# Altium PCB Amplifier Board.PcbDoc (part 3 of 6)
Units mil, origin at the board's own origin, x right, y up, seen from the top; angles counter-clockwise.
Board outline 6000 x 2640 mil, 6 copper layers (Top Layer, GND, VCC, BASES, GND (Plane3), Bottom Layer), stack 63.9 mil thick; 884 components, 484 nets, 2029 pads, 464 vias.
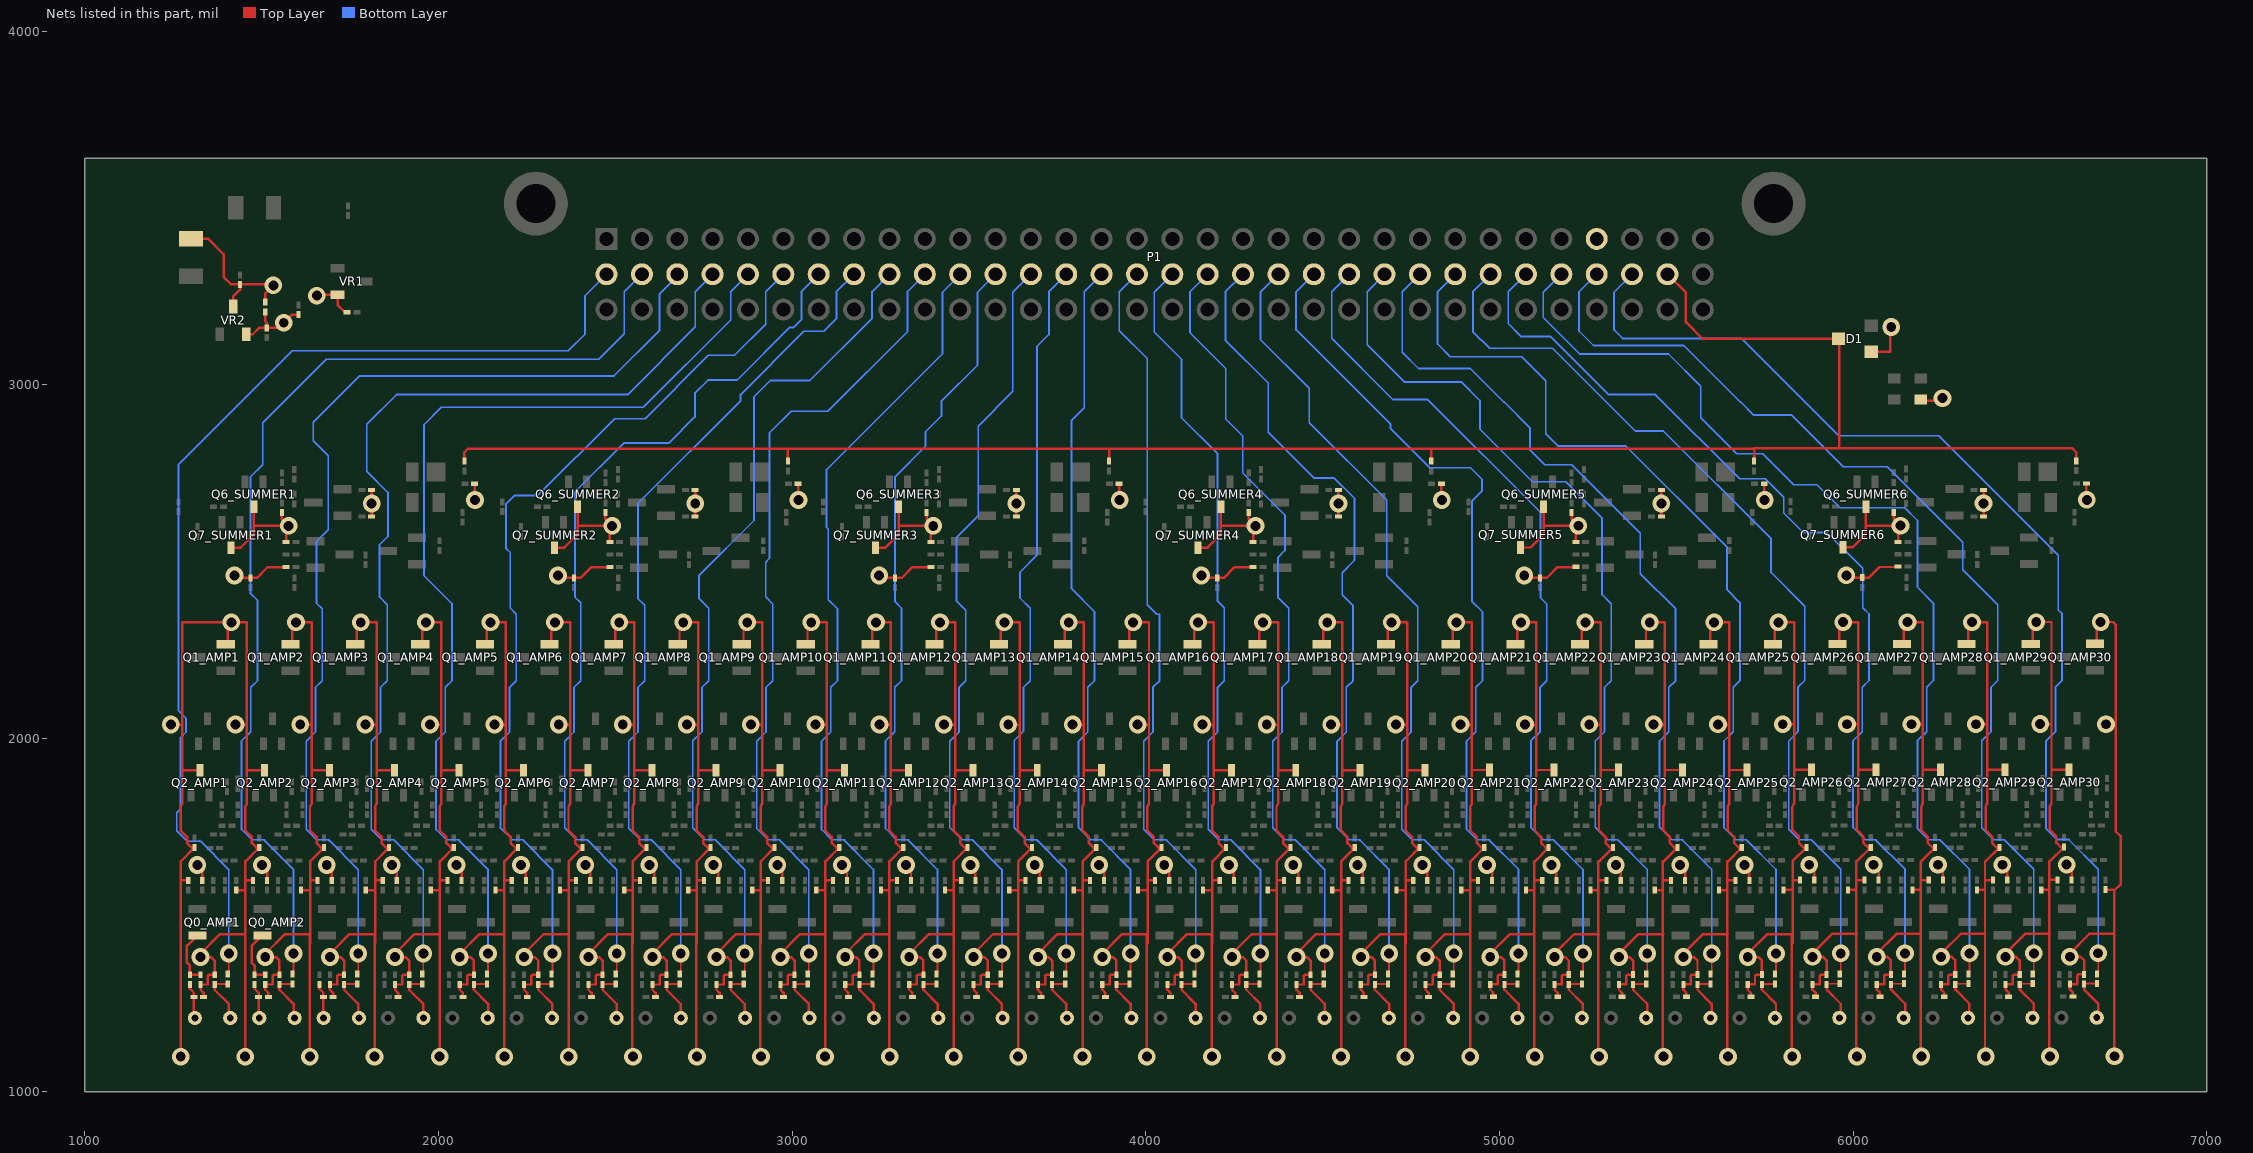
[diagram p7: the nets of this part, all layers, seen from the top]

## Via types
v1: diameter 50, hole 28, Top Layer to Bottom Layer, 433 vias
v2: diameter 50, hole 28, Top Layer to Bottom Layer, tented top, 31 vias

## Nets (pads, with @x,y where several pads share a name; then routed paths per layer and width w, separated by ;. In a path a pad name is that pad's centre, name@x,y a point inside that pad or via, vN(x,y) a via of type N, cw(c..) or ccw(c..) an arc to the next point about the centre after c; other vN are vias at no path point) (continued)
BASE2: C11.2 R23.1 R26.2 RBi_AMP1.1 RBi_AMP2.1 RBi_AMP3.1 RBi_AMP4.1 RBi_AMP5.1 RBi_AMP6.1 RBi_AMP7.1 RBi_AMP8.1 RBi_AMP9.1 RBi_AMP10.1 RBi_AMP11.1 RBi_AMP12.1 RBi_AMP13.1 RBi_AMP14.1 RBi_AMP15.1 RBi_AMP16.1 RBi_AMP17.1 RBi_AMP18.1 RBi_AMP19.1 RBi_AMP20.1 RBi_AMP21.1 RBi_AMP22.1 RBi_AMP23.1 RBi_AMP24.1 RBi_AMP25.1 RBi_AMP26.1 RBi_AMP27.1 RBi_AMP28.1 RBi_AMP29.1 RBi_AMP30.1 VR2.3 | length 1924.2
  Top Layer w7: R23.1@1300,3413.15 1347.85,3413.15 1392,3369 1392,3305 1412.4,3284.6 v1@1529.4,3284.6 ; v1(1318,1642) 1332,1628 RBi_AMP1.1@1332,1598.56 ; VR2.3@1419,3221.37 1419,3249 1439,3269 R26.2@1439,3283.22 ; v1(1501,1642) 1515,1628 RBi_AMP2.1@1515,1598.56 ; C11.2@1510,3233.78 1510,3258 v1(1533,3281) ; v1(1684,1642) 1698,1628 RBi_AMP3.1@1698,1598.56 ; v1(1868,1642) 1882,1628 RBi_AMP4.1@1882,1598.56 ; v1(2051,1642) 2065,1628 RBi_AMP5.1@2065,1598.56 ; v1(2233,1642) 2247,1628 RBi_AMP6.1@2247,1598.56 ; v1(2415,1642) 2429,1628 RBi_AMP7.1@2429,1598.56 ; v1(2596,1642) 2610,1628 RBi_AMP8.1@2610,1598.56 ; v1(2777,1642) 2791,1628 RBi_AMP9.1@2791,1598.56 ; v1(2958,1642) 2972,1628 RBi_AMP10.1@2972,1598.56 ; v1(3141,1642) 3155,1628 RBi_AMP11.1@3155,1598.56 ; v1(3322,1642) 3336,1628 RBi_AMP12.1@3336,1598.56 ; v1(3504,1642) 3518,1628 RBi_AMP13.1@3518,1598.56 ; v1(3686,1642) 3700,1628 RBi_AMP14.1@3700,1598.56 ; v1(3868,1642) 3882,1628 RBi_AMP15.1@3882,1598.56 ; v1(4052,1642) 4066,1628 RBi_AMP16.1@4066,1598.56 ; v1(4235,1642) 4249,1628 RBi_AMP17.1@4249,1598.56 ; v1(4417,1642) 4431,1628 RBi_AMP18.1@4431,1598.56 ; v1(4599,1642) 4613,1628 RBi_AMP19.1@4613,1598.56 ; v1(4782,1642) 4796,1628 RBi_AMP20.1@4796,1598.56 ; v1(4965,1642.1) 4979,1628.1 RBi_AMP21.1@4979,1598.66 ; v1(5147,1642.1) 5161,1628.1 RBi_AMP22.1@5161,1598.66 ; v1(5329,1642.1) 5343,1628.1 RBi_AMP23.1@5343,1598.66 ; v1(5511,1642.1) 5525,1628.1 RBi_AMP24.1@5525,1598.66 ; v1(5693,1642.1) 5707,1628.1 RBi_AMP25.1@5707,1598.66 ; v1(5876,1642.57) 5890,1628.57 RBi_AMP26.1@5890,1599.13 ; v1(6058,1642.57) 6072,1628.57 RBi_AMP27.1@6072,1599.13 ; v1(6240,1642.57) 6254,1628.57 RBi_AMP28.1@6254,1599.13 ; v1(6422,1642.57) 6436,1628.57 RBi_AMP29.1@6436,1599.13 ; v1(6604,1643) 6618,1629 RBi_AMP30.1@6618,1599.56
BIAS1_SUMMER1: P1.B1 R18_AMP1.1 | length 3053.7
  Top Layer w5: R18_AMP1.1@1407,1334.83 v1(1407,1391.43) v1@1407,1392.43
  Bottom Layer w5: 1324.56,1711.44 1326.71,1709.29 ; 1328.27,1709.29 1326.71,1709.29 ; v1@1407,1381.56 v1(1407,1391.43) 1407,1629 1327.49,1708.51 1326.71,1709.29 ; P1.B1@2475,3312.36 2414,3251.36 2414,3143 2367,3096 1586,3096 1265,2775 1265,2078 1286,2057 1286,2017.99 1270.5,2002.49 1270.5,1800.5 1260,1790 1260,1739 1289.71,1709.29 1326.71,1709.29
BIAS1_SUMMER2: P1.B6 R18_AMP6.1 | length 2554
  Top Layer w5: R18_AMP6.1@2322,1334.83 v1(2322,1391.43) v1@2322,1392.43
  Bottom Layer w5: 2239.56,1711.44 2322,1629 v1(2322,1391.43) v1@2322,1381.56 ; 2239.56,1713 2209,1713 2174.84,1747.16 2174.84,1991.84 2201,2018 2201,2144 2220,2163 2220,2351 2202.5,2368.5 2202.5,2525.5 2190.5,2537.5 2190.5,2662.5 2215,2687 2281,2687 2498,2904 2584,2904 2763,3083 2837,3083 2925,3171 2925,3262.36 P1.B6@2975,3312.36
BIAS1_SUMMER3: P1.B11 R18_AMP11.1 | length 2265
  Top Layer w5: R18_AMP11.1@3230,1334.83 v1(3230,1391.43) v1@3230,1392.43
  Bottom Layer w5: 3147.56,1711.44 3230,1629 v1(3230,1391.43) v1@3230,1381.56 ; 3147.56,1713 3112.43,1713 3082.84,1742.59 3082.84,1991.84 3109,2018 3109,2144 3128,2163 3128,2366 3102,2392 3102,2592 3097,2597 3097,2760 3425,3088 3425,3261 3475.68,3311.68 P1.B11@3482,3318
BIAS1_SUMMER4: P1.B16 R18_AMP16.1 | length 2159.7
  Top Layer w5: R18_AMP16.1@4141,1334.83 v1(4141,1391.43) v1@4141,1392.43
  Bottom Layer w5: P1.B16@3975,3312.36 3925,3262.36 3925,3153 4004,3074 4004,2378 4031,2351 4039,2351 4039,2163 4020,2144 4020,2018 3993.84,1991.84 3993.84,1742.59 4023.43,1713 4058.56,1713 ; 4058.56,1711.44 4141,1629 v1(4141,1391.43) v1@4141,1381.56
BIAS1_SUMMER5: P1.B21 R18_AMP21.1 | length 2417.4
  Top Layer w5: R18_AMP21.1@5054,1334.93 v1(5054,1391.53) v1@5054,1392.53
  Bottom Layer w5: P1.B21@4475,3312.36 4425,3262.36 4425,3155 4692.2,2887.8 4692.2,2875.8 4803,2765 4918,2765 4951,2732 4951,2700 4922,2671 4922,2388 4952,2358 4952,2163.1 4933,2144.1 4933,2018.38 4906.84,1992.22 4906.84,1742.69 4936.43,1713.1 4971.56,1713.1 ; 4971.56,1711.54 5054,1629.1 v1(5054,1391.53) v1@5054,1381.66
BIAS1_SUMMER6: P1.B26 R18_AMP26.1 | length 2646.3
  Top Layer w5: R18_AMP26.1@5965,1335.4 v1(5965,1392) v1@5965,1393
  Bottom Layer w5: P1.B26@4975,3312.36 4925,3262.36 4925,3150 4972,3103 5150,3103 5384,2869 5463,2869 5768,2564 5768,2469 5863,2374 5863,2163.57 5844,2144.57 5844,2018.62 5817.84,1992.47 5817.84,1743.16 5847.43,1713.57 5882.56,1713.57 ; 5882.56,1712.01 5965,1629.57 v1(5965,1392) v1@5965,1382.13
BIAS2_SUMMER1: P1.B2 R18_AMP2.1 | length 3005
  Top Layer w5: R18_AMP2.1@1590,1334.83 v1(1590,1391.43) v1@1590,1392.43
  Bottom Layer w5: 1507.56,1711.44 1590,1629 v1(1590,1391.43) v1@1590,1381.56 ; 1507.56,1713 1472.43,1713 1442.84,1742.59 1442.84,1992.84 1469,2019 1469,2144 1488,2163 1488,2390.44 1468,2410.44 1468,2739 1503,2774 1503,2892 1683,3072 2453,3072 2525,3144 2525,3262.36 P1.B2@2575,3312.36
BIAS2_SUMMER2: P1.B7 R18_AMP7.1 | length 2505.3
  Top Layer w5: R18_AMP7.1@2504,1334.83 v1(2504,1391.43) v1@2504,1392.43
  Bottom Layer w5: 2421.56,1711.44 2504,1629 v1(2504,1391.43) v1@2504,1381.56 ; 2421.56,1713 2391,1713 2356.84,1747.16 2356.84,1991.84 2383,2018 2383,2144 2402,2163 2402,2383 2386,2399 2386,2697 2524,2835 2651,2835 2725,2909 2725,2976 2762,3013 2844,3013 2993,3162 3004,3162 3026,3184 3026,3263.36 P1.B7@3075,3312.36
BIAS2_SUMMER3: P1.B12 R18_AMP12.1 | length 2210.7
  Top Layer w5: R18_AMP12.1@3411,1334.83 v1(3411,1391.43) v1@3411,1392.43
  Bottom Layer w5: 3328.56,1711.44 3411,1629 v1(3411,1391.43) v1@3411,1381.56 ; 3328.56,1713 3296,1713 3263.84,1745.16 3263.84,1992.84 3290,2019 3290,2144 3309,2163 3309,2368 3291,2386 3291,2740 3377,2826 3377,2866.5 3422,2911.5 3422,2953 3524,3055 3524,3261.36 P1.B12@3575,3312.36
BIAS2_SUMMER4: P1.B17 R18_AMP17.1 | length 2190.2
  Top Layer w5: R18_AMP17.1@4324,1334.83 v1(4324,1391.43) v1@4324,1392.43
  Bottom Layer w5: P1.B17@4075,3312.36 4024,3261.36 4024,3149 4101,3072 4101,2907 4203,2805 4203,2388 4222,2369 4222,2163 4203,2144 4203,2018 4176.84,1991.84 4176.84,1742.59 4206.43,1713 4241.56,1713 ; 4241.56,1711.44 4324,1629 v1(4324,1391.43) v1@4324,1381.56
BIAS2_SUMMER5: P1.B22 R18_AMP22.1 | length 2413.3
  Top Layer w5: R18_AMP22.1@5236,1334.93 v1(5236,1391.53) v1@5236,1392.53
  Bottom Layer w5: P1.B22@4575,3312.36 4526,3263.36 4526,3131 4699,2958 4797,2958 5116,2639 5116,2398 5134,2380 5134,2163.1 5115,2144.1 5115,2018.96 5088.84,1992.8 5088.84,1748.16 5123.9,1713.1 5153.56,1713.1 ; 5153.56,1711.54 5236,1629.1 v1(5236,1391.53) v1@5236,1381.66
BIAS2_SUMMER6: P1.B27 R18_AMP27.1 | length 2734.6
  Top Layer w5: R18_AMP27.1@6147,1335.4 v1(6147,1392) v1@6147,1393
  Bottom Layer w5: P1.B27@5075,3312.36 5025,3262.36 5025,3173 5062,3136 5145.28,3136 5309.28,2972 5441,2972 5679,2734 5752,2734 5804,2682 5804,2637.17 5859.17,2582 5926,2582 6027,2481 6027,2369.57 6045,2351.57 6045,2163.57 6026,2144.57 6026,2019 5999.84,1992.84 5999.84,1748.16 6034.43,1713.57 6064.56,1713.57 ; 6064.56,1712.01 6147,1629.57 v1(6147,1392) v1@6147,1382.13
BIAS3_SUMMER1: P1.B3 R18_AMP3.1 | length 2979.5
  Top Layer w5: R18_AMP3.1@1773,1334.83 v1(1773,1391.43) v1@1773,1392.43
  Bottom Layer w5: 1690.56,1711.44 1773,1629 v1(1773,1391.43) v1@1773,1381.56 ; 1690.56,1713 1655.43,1713 1625.84,1742.59 1625.84,1992.2 1652,2018.36 1652,2144 1671,2163 1671,2366 1655,2382 1655,2556.9 1688,2589.9 1688,2799 1646,2841 1646,2894 1777,3025 2496,3025 2625,3154 2625,3257 2677.68,3309.68 P1.B3@2684,3316
BIAS3_SUMMER2: P1.B8 R18_AMP8.1 | length 2378.7
  Top Layer w5: R18_AMP8.1@2685,1334.83 v1(2685,1391.43) v1@2685,1392.43
  Bottom Layer w5: 2602.56,1711.44 2685,1629 v1(2685,1391.43) v1@2685,1381.56 ; 2602.56,1713 2571,1713 2537.84,1746.16 2537.84,1991.84 2564,2018 2564,2144 2583,2163 2583,2376 2564,2395 2564,2665 2854,2955 2854,2972 3033,3151 3089,3151 3125,3187 3125,3262.36 P1.B8@3175,3312.36
BIAS3_SUMMER3: P1.B13 R18_AMP13.1 | length 2181.7
  Top Layer w5: R18_AMP13.1@3593,1334.83 v1(3593,1391.43) v1@3593,1392.43
  Bottom Layer w5: 3510.56,1711.44 3593,1629 v1(3593,1391.43) v1@3593,1381.56 ; 3510.56,1713 3480.79,1713 3445.84,1747.94 3445.84,1991.84 3472,2018 3472,2144 3491,2163 3491,2362 3465,2388 3465,2568.95 3526,2629.95 3526,2883 3624,2981 3624,3261.36 P1.B13@3675,3312.36
BIAS3_SUMMER4: P1.B18 R18_AMP18.1 | length 2236.8
  Top Layer w5: R18_AMP18.1@4506,1334.83 v1(4506,1391.43) v1@4506,1392.43
  Bottom Layer w5: P1.B18@4175,3312.36 4125,3262.36 4125,3147 4226,3046 4226,2903 4274,2855 4274,2750.5 4393.44,2631.06 4393.44,2531.44 4374,2512 4374,2398 4404,2368 4404,2163 4385,2144 4385,2018 4358.84,1991.84 4358.84,1747.16 4393,1713 4423.56,1713 ; 4423.56,1711.44 4506,1629 v1(4506,1391.43) v1@4506,1381.56
BIAS3_SUMMER5: P1.B23 R18_AMP23.1 | length 2539.1
  Top Layer w5: R18_AMP23.1@5418,1334.93 v1(5418,1391.53) v1@5418,1392.53
  Bottom Layer w5: P1.B23@4675,3312.36 4626,3263.36 4626,3113 4731,3008 4892,3008 4945,2955 4945,2874 5093.46,2725.54 5187.12,2725.54 5290.26,2622.4 5290.26,2406.74 5316,2381 5316,2163.1 5297,2144.1 5297,2018.77 5270.84,1992.61 5270.84,1748.16 5305.9,1713.1 5335.56,1713.1 ; 5335.56,1711.54 5418,1629.1 v1(5418,1391.53) v1@5418,1381.66
BIAS3_SUMMER6: P1.B28 R18_AMP28.1 | length 2898.7
  Top Layer w5: R18_AMP28.1@6329,1335.4 v1(6329,1392) v1@6329,1393
  Bottom Layer w5: P1.B28@5175,3312.36 5124,3261.36 5124,3190 5227,3087 5478,3087 5569,2996 5569,2906.7 5670.7,2805 5744.7,2805 5832.7,2717 5898,2717 5963,2652 6146.16,2652 6182,2616.16 6182,2427 6227,2382 6227,2163.57 6208,2144.57 6208,2019 6181.84,1992.84 6181.84,1746.16 6214.43,1713.57 6246.56,1713.57 ; 6246.56,1712.01 6329,1629.57 v1(6329,1392) v1@6329,1382.13
BIAS4_SUMMER1: P1.B4 R18_AMP4.1 | length 2919
  Top Layer w5: R18_AMP4.1@1957,1334.83 v1(1957,1391.43) v1@1957,1392.43
  Bottom Layer w5: 1874.56,1711.44 1957,1629 v1(1957,1391.43) v1@1957,1381.56 ; 1874.56,1713 1839.43,1713 1809.84,1742.59 1809.84,1991.84 1836,2018 1836,2144 1855,2163 1855,2378 1833,2400 1833,2547.09 1857,2571.09 1857,2695 1797,2755 1797,2888 1881,2972 2534.64,2972 2726,3163.36 2726,3263.36 P1.B4@2775,3312.36
BIAS4_SUMMER2: P1.B9 R18_AMP9.1 | length 2384.7
  Top Layer w5: R18_AMP9.1@2866,1334.83 v1(2866,1391.43) v1@2866,1392.43
  Bottom Layer w5: 2783.56,1711.44 2866,1629 v1(2866,1391.43) v1@2866,1381.56 ; 2783.56,1713 2753,1713 2718.84,1747.16 2718.84,1992.84 2745,2019 2745,2144 2764,2163 2764,2368 2736.23,2395.77 2736.23,2460.13 2892,2615.9 2892,2966 2938,3012 3050,3012 3226,3188 3226,3263.36 P1.B9@3275,3312.36
BIAS4_SUMMER3: P1.B14 R18_AMP14.1 | length 2150.5
  Top Layer w5: R18_AMP14.1@3775,1334.83 v1(3775,1391.43) v1@3775,1392.43
  Bottom Layer w5: 3692.56,1711.44 3775,1629 v1(3775,1391.43) v1@3775,1381.56 ; 3692.56,1713 3662,1713 3627.84,1747.16 3627.84,1993.84 3654,2020 3654,2144 3673,2163 3673,2368 3644.23,2396.77 3644.23,2469.79 3692,2517.56 3692,3108 3726,3142 3726,3263.36 P1.B14@3775,3312.36
BIAS4_SUMMER4: P1.B19 R18_AMP19.1 | length 2316.6
  Top Layer w5: R18_AMP19.1@4688,1334.83 v1(4688,1391.43) v1@4688,1392.43
  Bottom Layer w5: P1.B19@4275,3312.36 4225,3262.36 4225,3126 4346,3005 4346,2866 4476.1,2735.9 4533.1,2735.9 4590,2679 4590,2503.56 4555.23,2468.79 4555.23,2405.77 4586,2375 4586,2163 4567,2144 4567,2018 4540.84,1991.84 4540.84,1747.52 4575.36,1713 4605.56,1713 ; 4605.56,1711.44 4688,1629 v1(4688,1391.43) v1@4688,1381.56
BIAS4_SUMMER5: P1.B24 R18_AMP24.1 | length 2555.6
  Top Layer w5: R18_AMP24.1@5600,1334.93 v1(5600,1391.53) v1@5600,1392.53
  Bottom Layer w5: P1.B24@4775,3312.36 4725,3262.36 4725,3092 4771,3046 4917,3046 5012,2951 5013,2951 5086,2878 5086,2816 5128,2774 5204.5,2774 5398,2580.5 5398,2466 5498,2366 5498,2163.1 5479,2144.1 5479,2018.58 5452.84,1992.42 5452.84,1748.16 5487.9,1713.1 5517.56,1713.1 ; 5517.56,1711.54 5600,1629.1 v1(5600,1391.53) v1@5600,1381.66
BIAS4_SUMMER6: P1.B29 R18_AMP29.1 | length 2881.2
  Top Layer w5: R18_AMP29.1@6511,1335.4 v1(6511,1392) v1@6511,1393
  Bottom Layer w5: P1.B29@5275,3312.36 5225,3262.36 5225,3152 5266,3111 5521,3111 5681,2951 5682,2951 5719,2914 5826,2914 5972,2768 6097,2768 6310,2555 6310,2476.79 6409,2377.79 6409,2163.57 6390,2144.57 6390,2019 6363.84,1992.84 6363.84,1747.16 6397.43,1713.57 6428.56,1713.57 ; 6428.56,1712.01 6511,1629.57 v1(6511,1392) v1@6511,1382.13
BIAS5_SUMMER1: P1.B5 R18_AMP5.1 | length 2833.7
  Top Layer w5: R18_AMP5.1@2140,1334.83 v1(2140,1391.43) v1@2140,1392.43
  Bottom Layer w5: 2057.56,1711.44 2140,1629 v1(2140,1391.43) v1@2140,1381.56 ; 2057.56,1713 2022.43,1713 1992.84,1742.59 1992.84,1991.84 2019,2018 2019,2144 2038,2163 2038,2381 1959,2460 1959,2887 2008,2936 2579,2936 2826,3183 2826,3263.36 P1.B5@2875,3312.36
BIAS5_SUMMER2: P1.B10 R18_AMP10.1 | length 2341.2
  Top Layer w5: R18_AMP10.1@3047,1334.83 v1(3047,1391.43) v1@3047,1392.43
  Bottom Layer w5: 2964.56,1711.44 3047,1629 v1(3047,1391.43) v1@3047,1381.56 ; 2964.56,1713 2932,1713 2899.84,1745.16 2899.84,1991.84 2926,2018 2926,2144 2945,2163 2945,2380 2925,2400 2925,2498 2936,2509 2936,2864 2997,2925 3101,2925 3326,3150 3326,3263.36 P1.B10@3375,3312.36
BIAS5_SUMMER3: P1.B15 R18_AMP15.1 | length 2146.5
  Top Layer w5: R18_AMP15.1@3957,1334.83 v1(3957,1391.43) v1@3957,1392.43
  Bottom Layer w5: 3874.56,1711.44 3957,1629 v1(3957,1391.43) v1@3957,1381.56 ; 3874.56,1713 3844,1713 3809.84,1747.16 3809.84,1991.84 3836,2018 3836,2144 3855,2163 3855,2358 3790,2423 3790,2899 3826,2935 3826,3263.36 P1.B15@3875,3312.36
BIAS5_SUMMER4: P1.B20 R18_AMP20.1 | length 2292.5
  Top Layer w5: R18_AMP20.1@4871,1334.83 v1(4871,1391.43) v1@4871,1392.43
  Bottom Layer w5: P1.B20@4375,3312.36 4324,3261.36 4324,3128 4462,2990 4462,2893 4681,2674 4681,2460 4769,2372 4769,2163 4750,2144 4750,2018 4723.84,1991.84 4723.84,1742.59 4753.43,1713 4788.56,1713 ; 4788.56,1711.44 4871,1629 v1(4871,1391.43) v1@4871,1381.56
BIAS5_SUMMER5: P1.B25 R18_AMP25.1 | length 2689.7
  Top Layer w5: R18_AMP25.1@5782,1334.93 v1(5782,1391.53) v1@5782,1392.53
  Bottom Layer w5: P1.B25@4875,3312.36 4825,3262.36 4825,3115 4861,3079 5063,3079 5131,3011 5131,2861 5165,2827 5356.5,2827 5643.6,2539.91 5643.6,2420.4 5680,2384 5680,2163.1 5661,2144.1 5661,2018.77 5634.84,1992.61 5634.84,1747.16 5668.9,1713.1 5699.56,1713.1 ; 5699.56,1711.54 5782,1629.1 v1(5782,1391.53) v1@5782,1381.66
BIAS5_SUMMER6: P1.B30 R18_AMP30.1 | length 2994.7
  Top Layer w5: R18_AMP30.1@6693,1335.83 v1(6693,1392.43) v1@6693,1393.43
  Bottom Layer w5: P1.B30@5375,3312.36 5324,3261.36 5324,3155 5348,3131 5684,3131 5959,2856 6242,2856 6580,2518 6580,2363 ; 6580,2362.57 6580,2363 ; 6610.56,1712.44 6693,1630 v1(6693,1392.43) v1@6693,1382.56 ; 6610.56,1714 6576,1714 6545.84,1744.16 6545.84,1992.84 6572,2019 6572,2145 6591,2164 6591,2352 6580,2363
GAINMODE: D1.2 P1.B31 RG_SUMMER1.2 RG_SUMMER2.2 RG_SUMMER3.2 RG_SUMMER4.2 RG_SUMMER5.2 RG_SUMMER6.2 | length 5671.5
  Top Layer w7: RG_SUMMER1.2@2073,2783.78 2073,2809 2083,2819 3896,2819 ; RG_SUMMER2.2@2988,2783.78 2988,2817 ; RG_SUMMER3.2@3896,2783.78 3896,2819 ; RG_SUMMER4.2@4807,2783.78 4807,2817 ; P1.B31@5475,3312.36 5527,3260.36 5527,3177 5574,3130 D1.2@5958.74,3130 ; RG_SUMMER5.2@5720,2783.88 5720,2819 ; 5961,2821 D1.2@5961,3130 ; RG_SUMMER6.2@6631,2784.35 6631,2809 6620,2820 5720,2820 5720,2819 ; 3896,2819 5720,2819
GND: C1_AMP1.2 C1_AMP2.2 C1_AMP3.2 C1_AMP4.2 C1_AMP5.2 C1_AMP6.2 C1_AMP7.2 C1_AMP8.2 C1_AMP9.2 C1_AMP10.2 C1_AMP11.2 C1_AMP12.2 C1_AMP13.2 C1_AMP14.2 C1_AMP15.2 C1_AMP16.2 C1_AMP17.2 C1_AMP18.2 C1_AMP19.2 C1_AMP20.2 C1_AMP21.2 C1_AMP22.2 C1_AMP23.2 C1_AMP24.2 C1_AMP25.2 C1_AMP26.2 C1_AMP27.2 C1_AMP28.2 C1_AMP29.2 C1_AMP30.2 C3_AMP1.1 C3_AMP2.1 C3_AMP3.1 C3_AMP4.1 C3_AMP5.1 C3_AMP6.1 C3_AMP7.1 C3_AMP8.1 C3_AMP9.1 C3_AMP10.1 C3_AMP11.1 C3_AMP12.1 C3_AMP13.1 C3_AMP14.1 C3_AMP15.1 C3_AMP16.1 C3_AMP17.1 C3_AMP18.1 C3_AMP19.1 C3_AMP20.1 C3_AMP21.1 C3_AMP22.1 C3_AMP23.1 C3_AMP24.1 C3_AMP25.1 C3_AMP26.1 C3_AMP27.1 C3_AMP28.1 C3_AMP29.1 C3_AMP30.1 C10.1 C11.1 CBi_AMP1.2 CBi_AMP2.2 CBi_AMP3.2 CBi_AMP4.2 CBi_AMP5.2 CBi_AMP6.2 CBi_AMP7.2 CBi_AMP8.2 CBi_AMP9.2 CBi_AMP10.2 CBi_AMP11.2 CBi_AMP12.2 CBi_AMP13.2 CBi_AMP14.2 CBi_AMP15.2 CBi_AMP16.2 CBi_AMP17.2 CBi_AMP18.2 CBi_AMP19.2 CBi_AMP20.2 CBi_AMP21.2 CBi_AMP22.2 CBi_AMP23.2 CBi_AMP24.2 CBi_AMP25.2 CBi_AMP26.2 CBi_AMP27.2 CBi_AMP28.2 CBi_AMP29.2 CBi_AMP30.2 CBi_SUMMER1.2 CBi_SUMMER2.2 CBi_SUMMER3.2 CBi_SUMMER4.2 CBi_SUMMER5.2 CBi_SUMMER6.2 CG_SUMMER1.2 CG_SUMMER2.2 CG_SUMMER3.2 CG_SUMMER4.2 CG_SUMMER5.2 CG_SUMMER6.2 D1.1 P1.A29 Q1_AMP1.2 Q1_AMP2.2 Q1_AMP3.2 Q1_AMP4.2 Q1_AMP5.2 Q1_AMP6.2 Q1_AMP7.2 Q1_AMP8.2 Q1_AMP9.2 Q1_AMP10.2 Q1_AMP11.2 Q1_AMP12.2 Q1_AMP13.2 Q1_AMP14.2 Q1_AMP15.2 Q1_AMP16.2 Q1_AMP17.2 Q1_AMP18.2 Q1_AMP19.2 Q1_AMP20.2 Q1_AMP21.2 Q1_AMP22.2 Q1_AMP23.2 Q1_AMP24.2 Q1_AMP25.2 Q1_AMP26.2 Q1_AMP27.2 Q1_AMP28.2 Q1_AMP29.2 Q1_AMP30.2 Q2_AMP1.3 Q2_AMP2.3 Q2_AMP3.3 Q2_AMP4.3 Q2_AMP5.3 Q2_AMP6.3 Q2_AMP7.3 Q2_AMP8.3 Q2_AMP9.3 Q2_AMP10.3 Q2_AMP11.3 Q2_AMP12.3 Q2_AMP13.3 Q2_AMP14.3 Q2_AMP15.3 Q2_AMP16.3 Q2_AMP17.3 Q2_AMP18.3 Q2_AMP19.3 Q2_AMP20.3 Q2_AMP21.3 Q2_AMP22.3 Q2_AMP23.3 Q2_AMP24.3 Q2_AMP25.3 Q2_AMP26.3 Q2_AMP27.3 Q2_AMP28.3 Q2_AMP29.3 Q2_AMP30.3 Q6_SUMMER1.3 Q6_SUMMER2.3 Q6_SUMMER3.3 Q6_SUMMER4.3 Q6_SUMMER5.3 Q6_SUMMER6.3 Q7_SUMMER1.3 Q7_SUMMER2.3 Q7_SUMMER3.3 Q7_SUMMER4.3 Q7_SUMMER5.3 Q7_SUMMER6.3 R1_AMP1.1 R1_AMP2.1 R1_AMP3.1 R1_AMP4.1 R1_AMP5.1 R1_AMP6.1 R1_AMP7.1 R1_AMP8.1 R1_AMP9.1 R1_AMP10.1 R1_AMP11.1 R1_AMP12.1 R1_AMP13.1 R1_AMP14.1 R1_AMP15.1 R1_AMP16.1 R1_AMP17.1 R1_AMP18.1 R1_AMP19.1 R1_AMP20.1 R1_AMP21.1 R1_AMP22.1 R1_AMP23.1 R1_AMP24.1 R1_AMP25.1 R1_AMP26.1 R1_AMP27.1 R1_AMP28.1 R1_AMP29.1 R1_AMP30.1 R3_AMP1.1 R3_AMP2.1 R3_AMP3.1 R3_AMP4.1 R3_AMP5.1 R3_AMP6.1 R3_AMP7.1 R3_AMP8.1 R3_AMP9.1 R3_AMP10.1 R3_AMP11.1 R3_AMP12.1 R3_AMP13.1 R3_AMP14.1 R3_AMP15.1 R3_AMP16.1 R3_AMP17.1 R3_AMP18.1 R3_AMP19.1 R3_AMP20.1 R3_AMP21.1 R3_AMP22.1 R3_AMP23.1 R3_AMP24.1 R3_AMP25.1 R3_AMP26.1 R3_AMP27.1 R3_AMP28.1 R3_AMP29.1 R3_AMP30.1 R9_SUMMER1.1 R9_SUMMER2.1 R9_SUMMER3.1 R9_SUMMER4.1 R9_SUMMER5.1 R9_SUMMER6.1 R12_SUMMER1.1 R12_SUMMER2.1 R12_SUMMER3.1 R12_SUMMER4.1 R12_SUMMER5.1 R12_SUMMER6.1 R14_SUMMER1.1 R14_SUMMER2.1 R14_SUMMER3.1 R14_SUMMER4.1 R14_SUMMER5.1 R14_SUMMER6.1 R17_SUMMER1.1 R17_SUMMER2.1 R17_SUMMER3.1 R17_SUMMER4.1 R17_SUMMER5.1 R17_SUMMER6.1 R19_AMP1.1 R19_AMP2.1 R19_AMP3.1 R19_AMP4.1 R19_AMP5.1 R19_AMP6.1 R19_AMP7.1 R19_AMP8.1 R19_AMP9.1 R19_AMP10.1 R19_AMP11.1 R19_AMP12.1 R19_AMP13.1 R19_AMP14.1 R19_AMP15.1 R19_AMP16.1 R19_AMP17.1 R19_AMP18.1 R19_AMP19.1 R19_AMP20.1 R19_AMP21.1 R19_AMP22.1 R19_AMP23.1 R19_AMP24.1 R19_AMP25.1 R19_AMP26.1 R19_AMP27.1 R19_AMP28.1 R19_AMP29.1 R19_AMP30.1 R22.2 R24.2 R27.2 RC_SUMMER1.1 RC_SUMMER2.1 RC_SUMMER3.1 RC_SUMMER4.1 RC_SUMMER5.1 RC_SUMMER6.1 VR1.2 VR2.2 | length 60322.5
  Top Layer w7: v1@1261,2039 1274,2039 ; v2(1271,1100) 1271,1652.22 R3_AMP1.1@1310,1691.22 1301.78,1691.22 1289,1704 1289,1721.5 1270.5,1740 1270.5,1806.5 1274,1814 1275,1815 1275,2328 v1(1414,2328) 1403.34,2317.34 Q1_AMP1.2@1403.34,2266.4 ; 1271.22,1598.56 CBi_AMP1.2@1292,1598.56 ; 1277.57,1910.43 Q2_AMP1.3@1325,1910.43 ; R19_AMP1.1@1335.78,1269 1335.78,1280.22 1327,1289 R1_AMP1.1@1327,1304 1347.59,1304 1347.59,1328.37 1350.78,1331.56 C1_AMP1.2@1367,1331.56 1367,1371.56 1357,1381.56 v1(1327,1381.56) 1327,1391 1382.43,1446.43 1452,1446.43 ; Q7_SUMMER1.3@1413,2539.57 1440.57,2539.57 1478,2577 Q6_SUMMER1.3@1478,2654.57 ; v1(1423,2460.43) 1429.65,2453.78 1486.78,2453.78 1517,2484 R12_SUMMER1.1@1568.22,2484 ; C3_AMP1.1@1429,1571 1451.22,1571 ; v1@1432,2328 1458,2328 1458,1815 1457,1814 1453.5,1806.5 1453.5,1740 1472,1721.5 1472,1704 1484.78,1691.22 R3_AMP2.1@1493,1691.22 1454,1652.22 1454,1420 ; v1@1444,2039 1457,2039 ; v2(1453,1100) 1453,1445.43 ; 1454.22,1598.56 CBi_AMP2.2@1475,1598.56 ; VR2.2@1456.4,3142.63 1474.63,3142.63 1492.78,3160.78 1547.78,3160.78 1585.22,3198.22 R22.2@1604,3198.22 ; 1460.57,1910.43 Q2_AMP2.3@1508,1910.43 ; 1478,2601 v1(1576,2601) ; C11.1@1510,3207.6 1510,3179.56 1514,3175.56 R24.2@1514,3159.4 ; R19_AMP2.1@1518.78,1269 1518.78,1280.22 1510,1289 R1_AMP2.1@1510,1304 1530.59,1304 1530.59,1328.37 1533.78,1331.56 C1_AMP2.2@1550,1331.56 1550,1371.56 1540,1381.56 v1(1510,1381.56) 1510,1391 1565.43,1446.43 1635,1446.43 ; RC_SUMMER1.1@1557,2638.22 1557,2620 v1(1576,2601) ; CBi_SUMMER1.2@1569.22,2555 1569.22,2594.22 v1(1576,2601) ; Q1_AMP2.2@1586.34,2266.4 1586.34,2317.34 v1(1597,2328) ; C3_AMP2.1@1612,1571 1634.22,1571 ; v1@1615,2328 1641,2328 1641,1815 1640,1814 1636.5,1806.5 1636.5,1740 1655,1721.5 1655,1704 1667.78,1691.22 R3_AMP3.1@1676,1691.22 1637,1652.22 1637,1420 ; v1@1627,2039 1640,2039 ; v2(1636,1100) 1636,1445.43 ; 1637.22,1598.56 CBi_AMP3.2@1658,1598.56 ; 1643.57,1910.43 Q2_AMP3.3@1691,1910.43 ; v1@1658.6,3254.6 VR1.2@1714.63,3254.6 1714.63,3225.38 1735.01,3205 C10.1@1741.22,3205 ; R19_AMP3.1@1701.78,1269 1701.78,1280.22 1693,1289 R1_AMP3.1@1693,1304 1713.59,1304 1713.59,1328.37 1716.78,1331.56 C1_AMP3.2@1733,1331.56 1733,1371.56 1723,1381.56 v1(1693,1381.56) 1693,1391 1748.43,1446.43 1818,1446.43 ; Q1_AMP3.2@1769.34,2266.4 1769.34,2317.34 v1(1780,2328) ; C3_AMP3.1@1796,1571 1818.22,1571 ; v1@1799,2328 1825,2328 1825,1815 1824,1814 1820.5,1806.5 1820.5,1740 1839,1721.5 1839,1704 1851.78,1691.22 R3_AMP4.1@1860,1691.22 1821,1652.22 1821,1420 ; R17_SUMMER1.1@1810.78,2627 R14_SUMMER1.1@1810.78,2702 ; v1@1811,2039 1824,2039 ; v2(1819,1100) 1819,1445.43 ; 1821.22,1598.56 CBi_AMP4.2@1842,1598.56 ; 1827.57,1910.43 Q2_AMP4.3@1875,1910.43 ; R19_AMP4.1@1885.78,1269 1885.78,1280.22 1877,1289 R1_AMP4.1@1877,1304 1897.59,1304 1897.59,1328.37 1900.78,1331.56 C1_AMP4.2@1917,1331.56 1917,1371.56 1907,1381.56 v1(1877,1381.56) 1877,1391 1932.43,1446.43 2002,1446.43 ; Q1_AMP4.2@1953.34,2266.4 1953.34,2317.34 v1(1964,2328) ; C3_AMP4.1@1979,1571 2001.22,1571 ; v1@1982,2328 2008,2328 2008,1815 2007,1814 2003.5,1806.5 2003.5,1740 2022,1721.5 2022,1704 2034.78,1691.22 R3_AMP5.1@2043,1691.22 2004,1652.22 2004,1420 ; v1@1994,2039 2007,2039 ; v2(2003,1100) 2003,1445.43 ; 2004.22,1598.56 CBi_AMP5.2@2025,1598.56 ; 2010.57,1910.43 Q2_AMP5.3@2058,1910.43 ; R19_AMP5.1@2068.78,1269 2068.78,1280.22 2060,1289 R1_AMP5.1@2060,1304 2080.59,1304 2080.59,1328.37 2083.78,1331.56 C1_AMP5.2@2100,1331.56 2100,1371.56 2090,1381.56 v1(2060,1381.56) 2060,1391 2115.43,1446.43 2185,1446.43 ; v1@2101.78,2675.22 CG_SUMMER1.2@2101.78,2720 ; Q1_AMP5.2@2136.34,2266.4 2136.34,2317.34 v1(2147,2328) ; C3_AMP5.1@2161,1571 2183.22,1571 ; v1@2164,2328 2190,2328 2190,1815 2189,1814 2185.5,1806.5 2185.5,1740 2204,1721.5 2204,1704 2216.78,1691.22 R3_AMP6.1@2225,1691.22 2186,1652.22 v2(2186,1100) ; v1@2176,2039 2189,2039 ; 2186.22,1598.56 CBi_AMP6.2@2207,1598.56 ; 2192.57,1910.43 Q2_AMP6.3@2240,1910.43 ; R19_AMP6.1@2250.78,1269 2250.78,1280.22 2242,1289 R1_AMP6.1@2242,1304 2262.59,1304 2262.59,1328.37 2265.78,1331.56 C1_AMP6.2@2282,1331.56 2282,1371.56 2272,1381.56 v1(2242,1381.56) 2242,1391 2297.43,1446.43 2367,1446.43 ; Q1_AMP6.2@2318.34,2266.4 2318.34,2317.34 v1(2329,2328) ; Q7_SUMMER2.3@2328,2539.57 2355.57,2539.57 2393,2577 Q6_SUMMER2.3@2393,2654.57 ; v1(2338,2460.43) 2344.65,2453.78 2401.78,2453.78 2432,2484 R12_SUMMER2.1@2483.22,2484 ; C3_AMP6.1@2343,1571 2365.22,1571 ; v1@2346,2328 2372,2328 2372,1815 2371,1814 2367.5,1806.5 2367.5,1740 2386,1721.5 2386,1704 2398.78,1691.22 R3_AMP7.1@2407,1691.22 2368,1652.22 v2(2368,1100) ; v1@2358,2039 2371,2039 ; 2368.22,1598.56 CBi_AMP7.2@2389,1598.56 ; 2374.57,1910.43 Q2_AMP7.3@2422,1910.43 ; 2393,2601 v1(2491,2601) ; R19_AMP7.1@2432.78,1269 2432.78,1280.22 2424,1289 R1_AMP7.1@2424,1304 2444.59,1304 2444.59,1328.37 2447.78,1331.56 C1_AMP7.2@2464,1331.56 2464,1371.56 2454,1381.56 v1(2424,1381.56) 2424,1391 2479.43,1446.43 2548,1446.43 2548,1102 v2(2550,1100) ; RC_SUMMER2.1@2472,2638.22 2472,2620 v1(2491,2601) ; CBi_SUMMER2.2@2484.22,2555 2484.22,2594.22 v1(2491,2601) ; Q1_AMP7.2@2500.34,2266.4 2500.34,2317.34 v1(2511,2328) ; C3_AMP7.1@2524,1571 2546.22,1571 ; v1@2527,2328 2553,2328 2553,1815 2552,1814 2548.5,1806.5 2548.5,1740 2567,1721.5 2567,1704 2579.78,1691.22 R3_AMP8.1@2588,1691.22 2549,1652.22 2549,1420 ; v1@2539,2039 2552,2039 ; 2549.22,1598.56 CBi_AMP8.2@2570,1598.56 ; 2555.57,1910.43 Q2_AMP8.3@2603,1910.43 ; R19_AMP8.1@2613.78,1269 2613.78,1280.22 2605,1289 R1_AMP8.1@2605,1304 2625.59,1304 2625.59,1328.37 2628.78,1331.56 C1_AMP8.2@2645,1331.56 2645,1371.56 2635,1381.56 v1(2605,1381.56) 2605,1391 2660.43,1446.43 2728.75,1446.43 2728.75,1102.25 v2(2731,1100) ; Q1_AMP8.2@2681.34,2266.4 2681.34,2317.34 v1(2692,2328) ; C3_AMP8.1@2705,1571 2727.22,1571 ; v1@2708,2328 2734,2328 2734,1815 2733,1814 2729.5,1806.5 2729.5,1740 2748,1721.5 2748,1704 2760.78,1691.22 R3_AMP9.1@2769,1691.22 2730,1652.22 2730,1420 ; v1@2720,2039 2733,2039 ; R17_SUMMER2.1@2725.78,2627 R14_SUMMER2.1@2725.78,2702 ; 2730.22,1598.56 CBi_AMP9.2@2751,1598.56 ; 2736.57,1910.43 Q2_AMP9.3@2784,1910.43 ; R19_AMP9.1@2794.78,1269 2794.78,1280.22 2786,1289 R1_AMP9.1@2786,1304 2806.59,1304 2806.59,1328.37 2809.78,1331.56 C1_AMP9.2@2826,1331.56 2826,1371.56 2816,1381.56 v1(2786,1381.56) 2786,1391 2841.43,1446.43 2909.75,1446.43 2909.75,1102.25 v2(2912,1100) ; Q1_AMP9.2@2862.34,2266.4 2862.34,2317.34 v1(2873,2328) ; C3_AMP9.1@2886,1571 2908.22,1571 ; v1@2889,2328 2915,2328 2915,1815 2914,1814 2910.5,1806.5 2910.5,1740 2929,1721.5 2929,1704 2941.78,1691.22 R3_AMP10.1@2950,1691.22 2911,1652.22 2911,1420 ; v1@2901,2039 2914,2039 ; 2911.22,1598.56 CBi_AMP10.2@2932,1598.56 ; 2917.57,1910.43 Q2_AMP10.3@2965,1910.43 ; R19_AMP10.1@2975.78,1269 2975.78,1280.22 2967,1289 R1_AMP10.1@2967,1304 2987.59,1304 2987.59,1328.37 2990.78,1331.56 C1_AMP10.2@3007,1331.56 3007,1371.56 2997,1381.56 v1(2967,1381.56) 2967,1391 3022.43,1446.43 3092,1446.43 ; v1@3016.78,2675.22 CG_SUMMER2.2@3016.78,2720 ; Q1_AMP10.2@3043.34,2266.4 3043.34,2317.34 v1(3054,2328) ; C3_AMP10.1@3069,1571 3091.22,1571 ; v1@3072,2328 3098,2328 3098,1815 3097,1814 3093.5,1806.5 3093.5,1740 3112,1721.5 3112,1704 3124.78,1691.22 R3_AMP11.1@3133,1691.22 3094,1652.22 3094,1420 ; v1@3084,2039 3097,2039 ; v2(3093,1100) 3093,1445.43 ; 3094.22,1598.56 CBi_AMP11.2@3115,1598.56 ; 3100.57,1910.43 Q2_AMP11.3@3148,1910.43 ; R19_AMP11.1@3158.78,1269 3158.78,1280.22 3150,1289 R1_AMP11.1@3150,1304 3170.59,1304 3170.59,1328.37 3173.78,1331.56 C1_AMP11.2@3190,1331.56 3190,1371.56 3180,1381.56 v1(3150,1381.56) 3150,1391 3205.43,1446.43 3274,1446.43 3274,1102 v2(3276,1100) ; Q1_AMP11.2@3226.34,2266.4 3226.34,2317.34 v1(3237,2328) ; Q7_SUMMER3.3@3236,2539.57 3263.57,2539.57 3301,2577 Q6_SUMMER3.3@3301,2654.57 ; v1(3246,2460.43) 3252.65,2453.78 3309.78,2453.78 3340,2484 R12_SUMMER3.1@3391.22,2484 ; C3_AMP11.1@3250,1571 3272.22,1571 ; v1@3253,2328 3279,2328 3279,1815 3278,1814 3274.5,1806.5 3274.5,1740 3293,1721.5 3293,1704 3305.78,1691.22 R3_AMP12.1@3314,1691.22 3275,1652.22 3275,1420 ; v1@3265,2039 3278,2039 ; 3275.22,1598.56 CBi_AMP12.2@3296,1598.56 ; 3281.57,1910.43 Q2_AMP12.3@3329,1910.43 ; 3301,2601 v1(3399,2601) ; R19_AMP12.1@3339.78,1269 3339.78,1280.22 3331,1289 R1_AMP12.1@3331,1304 3351.59,1304 3351.59,1328.37 3354.78,1331.56 C1_AMP12.2@3371,1331.56 3371,1371.56 3361,1381.56 v1(3331,1381.56) 3331,1391 3386.43,1446.43 3456,1446.43 ; RC_SUMMER3.1@3380,2638.22 3380,2620 v1(3399,2601) ; CBi_SUMMER3.2@3392.22,2555 3392.22,2594.22 v1(3399,2601) ; Q1_AMP12.2@3407.34,2266.4 3407.34,2317.34 v1(3418,2328) ; C3_AMP12.1@3432,1571 3454.22,1571 ; v1@3435,2328 3461,2328 3461,1815 3460,1814 3456.5,1806.5 3456.5,1740 3475,1721.5 3475,1704 3487.78,1691.22 R3_AMP13.1@3496,1691.22 3457,1652.22 v2(3457,1100) ; v1@3447,2039 3460,2039 ; 3457.22,1598.56 CBi_AMP13.2@3478,1598.56 ; 3463.57,1910.43 Q2_AMP13.3@3511,1910.43 ; R19_AMP13.1@3521.78,1269 3521.78,1280.22 3513,1289 R1_AMP13.1@3513,1304 3533.59,1304 3533.59,1328.37 3536.78,1331.56 C1_AMP13.2@3553,1331.56 3553,1371.56 3543,1381.56 v1(3513,1381.56) 3513,1391 3568.43,1446.43 3638,1446.43 ; Q1_AMP13.2@3589.34,2266.4 3589.34,2317.34 v1(3600,2328) ; C3_AMP13.1@3614,1571 3636.22,1571 ; v1@3617,2328 3643,2328 3643,1815 3642,1814 3638.5,1806.5 3638.5,1740 3657,1721.5 3657,1704 3669.78,1691.22 R3_AMP14.1@3678,1691.22 3639,1652.22 v2(3639,1100) ; v1@3629,2039 3642,2039 ; R17_SUMMER3.1@3633.78,2627 R14_SUMMER3.1@3633.78,2702 ; 3639.22,1598.56 CBi_AMP14.2@3660,1598.56 ; 3645.57,1910.43 Q2_AMP14.3@3693,1910.43 ; R19_AMP14.1@3703.78,1269 3703.78,1280.22 3695,1289 R1_AMP14.1@3695,1304 3715.59,1304 3715.59,1328.37 3718.78,1331.56 C1_AMP14.2@3735,1331.56 3735,1371.56 3725,1381.56 v1(3695,1381.56) 3695,1391 3750.43,1446.43 3820,1446.43 ; Q1_AMP14.2@3771.34,2266.4 3771.34,2317.34 v1(3782,2328) ; C3_AMP14.1@3796,1571 3818.22,1571 ; v1@3799,2328 3825,2328 3825,1815 3824,1814 3820.5,1806.5 3820.5,1740 3839,1721.5 3839,1704 3851.78,1691.22 R3_AMP15.1@3860,1691.22 3821,1652.22 v2(3821,1100) ; v1@3811,2039 3824,2039 ; 3821.22,1598.56 CBi_AMP15.2@3842,1598.56 ; 3827.57,1910.43 Q2_AMP15.3@3875,1910.43 ; R19_AMP15.1@3885.78,1269 3885.78,1280.22 3877,1289 R1_AMP15.1@3877,1304 3897.59,1304 3897.59,1328.37 3900.78,1331.56 C1_AMP15.2@3917,1331.56 3917,1371.56 3907,1381.56 v1(3877,1381.56) 3877,1391 3932.43,1446.43 4002,1446.43 ; v1@3924.78,2675.22 CG_SUMMER3.2@3924.78,2720 ; Q1_AMP15.2@3953.34,2266.4 3953.34,2317.34 v1(3964,2328) ; C3_AMP15.1@3980,1571 4002.22,1571 ; v1@3983,2328 4009,2328 4009,1815 4008,1814 4004.5,1806.5 4004.5,1740 4023,1721.5 4023,1704 4035.78,1691.22 R3_AMP16.1@4044,1691.22 4005,1652.22 4005,1420 ; v1@3995,2039 4008,2039 ; v2(4003,1100) 4003,1445.43 ; 4005.22,1598.56 CBi_AMP16.2@4026,1598.56 ; 4011.57,1910.43 Q2_AMP16.3@4059,1910.43 ; R19_AMP16.1@4069.78,1269 4069.78,1280.22 4061,1289 R1_AMP16.1@4061,1304 4081.59,1304 4081.59,1328.37 4084.78,1331.56 C1_AMP16.2@4101,1331.56 4101,1371.56 4091,1381.56 v1(4061,1381.56) 4061,1391 4116.43,1446.43 4186,1446.43 ; Q1_AMP16.2@4137.34,2266.4 4137.34,2317.34 v1(4148,2328) ; Q7_SUMMER4.3@4147,2539.57 4174.57,2539.57 4212,2577 Q6_SUMMER4.3@4212,2654.57 ; v1(4157,2460.43) 4163.65,2453.78 4220.78,2453.78 4251,2484 R12_SUMMER4.1@4302.22,2484 ; C3_AMP16.1@4163,1571 4185.22,1571 ; v1@4166,2328 4192,2328 4192,1815 4191,1814 4187.5,1806.5 4187.5,1740 4206,1721.5 4206,1704 4218.78,1691.22 R3_AMP17.1@4227,1691.22 4188,1652.22 4188,1420 ; v1@4178,2039 4191,2039 ; v2(4187,1100) 4187,1445.43 ; 4188.22,1598.56 CBi_AMP17.2@4209,1598.56 ; 4194.57,1910.43 Q2_AMP17.3@4242,1910.43 ; 4212,2601 v1(4310,2601) ; R19_AMP17.1@4252.78,1269 4252.78,1280.22 4244,1289 R1_AMP17.1@4244,1304 4264.59,1304 4264.59,1328.37 4267.78,1331.56 C1_AMP17.2@4284,1331.56 4284,1371.56 4274,1381.56 v1(4244,1381.56) 4244,1391 4299.43,1446.43 4369,1446.43 ; RC_SUMMER4.1@4291,2638.22 4291,2620 v1(4310,2601) ; CBi_SUMMER4.2@4303.22,2555 4303.22,2594.22 v1(4310,2601) ; Q1_AMP17.2@4320.34,2266.4 4320.34,2317.34 v1(4331,2328) ; C3_AMP17.1@4345,1571 4367.22,1571 ; v1@4348,2328 4374,2328 4374,1815 4373,1814 4369.5,1806.5 4369.5,1740 4388,1721.5 4388,1704 4400.78,1691.22 R3_AMP18.1@4409,1691.22 4370,1652.22 v2(4370,1100) ; v1@4360,2039 4373,2039 ; 4370.22,1598.56 CBi_AMP18.2@4391,1598.56 ; 4376.57,1910.43 Q2_AMP18.3@4424,1910.43 ; R19_AMP18.1@4434.78,1269 4434.78,1280.22 4426,1289 R1_AMP18.1@4426,1304 4446.59,1304 4446.59,1328.37 4449.78,1331.56 C1_AMP18.2@4466,1331.56 4466,1371.56 4456,1381.56 v1(4426,1381.56) 4426,1391 4481.43,1446.43 4551,1446.43 ; Q1_AMP18.2@4502.34,2266.4 4502.34,2317.34 v1(4513,2328) ; C3_AMP18.1@4527,1571 4549.22,1571 ; v1@4530,2328 4556,2328 4556,1815 4555,1814 4551.5,1806.5 4551.5,1740 4570,1721.5 4570,1704 4582.78,1691.22 R3_AMP19.1@4591,1691.22 4552,1652.22 v2(4552,1100) ; v1@4542,2039 4555,2039 ; R17_SUMMER4.1@4544.78,2627 R14_SUMMER4.1@4544.78,2702 ; 4552.22,1598.56 CBi_AMP19.2@4573,1598.56 ; 4558.57,1910.43 Q2_AMP19.3@4606,1910.43 ; R19_AMP19.1@4616.78,1269 4616.78,1280.22 4608,1289 R1_AMP19.1@4608,1304 4628.59,1304 4628.59,1328.37 4631.78,1331.56 C1_AMP19.2@4648,1331.56 4648,1371.56 4638,1381.56 v1(4608,1381.56) 4608,1391 4663.43,1446.43 4733,1446.43 ; Q1_AMP19.2@4684.34,2266.4 4684.34,2317.34 v1(4695,2328) ; C3_AMP19.1@4710,1571 4732.22,1571 ; v1@4713,2328 4739,2328 4739,1815 4738,1814 4734.5,1806.5 4734.5,1740 4753,1721.5 4753,1704 4765.78,1691.22 R3_AMP20.1@4774,1691.22 4735,1652.22 4735,1420 ; v1@4725,2039 4738,2039 ; v2(4734,1100) 4734,1445.43 ; 4735.22,1598.56 CBi_AMP20.2@4756,1598.56 ; 4741.57,1910.43 Q2_AMP20.3@4789,1910.43 ; R19_AMP20.1@4799.78,1269 4799.78,1280.22 4791,1289 R1_AMP20.1@4791,1304 4811.59,1304 4811.59,1328.37 4814.78,1331.56 C1_AMP20.2@4831,1331.56 4831,1371.56 4821,1381.56 v1(4791,1381.56) 4791,1391 4846.43,1446.43 4916,1446.43 ; v1@4835.78,2675.22 CG_SUMMER4.2@4835.78,2720 ; Q1_AMP20.2@4867.34,2266.4 4867.34,2317.34 v1(4878,2328) ; C3_AMP20.1@4893,1571.1 4915.22,1571.1 ; v1@4896,2328.1 4922,2328.1 4922,1815.1 4921,1814.1 4917.5,1806.6 4917.5,1740.1 4936,1721.6 4936,1704.1 4948.78,1691.32 R3_AMP21.1@4957,1691.32 4918,1652.32 4918,1420.1 ; v1@4908,2039.1 4921,2039.1 ; v2(4917,1100) 4917,1445.43 ; 4918.22,1598.66 CBi_AMP21.2@4939,1598.66 ; 4924.57,1910.54 Q2_AMP21.3@4972,1910.54 ; R19_AMP21.1@4982.78,1269.1 4982.78,1280.32 4974,1289.1 R1_AMP21.1@4974,1304.1 4994.59,1304.1 4994.59,1328.48 4997.78,1331.66 C1_AMP21.2@5014,1331.66 5014,1371.66 5004,1381.66 v1(4974,1381.66) 4974,1391.1 5029.43,1446.53 5099,1446.53 ; Q1_AMP21.2@5050.34,2266.5 5050.34,2317.44 v1(5061,2328.1) ; Q7_SUMMER5.3@5060,2539.67 5087.57,2539.67 5125,2577.1 Q6_SUMMER5.3@5125,2654.67 ; v1(5070,2460.53) 5076.65,2453.88 5133.78,2453.88 5164,2484.1 R12_SUMMER5.1@5215.22,2484.1 ; C3_AMP21.1@5075,1571.1 5097.22,1571.1 ; v1@5078,2328.1 5104,2328.1 5104,1815.1 5103,1814.1 5099.5,1806.6 5099.5,1740.1 5118,1721.6 5118,1704.1 5130.78,1691.32 R3_AMP22.1@5139,1691.32 5100,1652.32 ; v1@5090,2039.1 5103,2039.1 ; v2@5098,1100.1 5098,1652.32 ; 5100.22,1598.66 CBi_AMP22.2@5121,1598.66 ; 5106.57,1910.54 Q2_AMP22.3@5154,1910.54 ; 5125,2601.1 v1(5223,2601.1) ; R19_AMP22.1@5164.78,1269.1 5164.78,1280.32 5156,1289.1 R1_AMP22.1@5156,1304.1 5176.59,1304.1 5176.59,1328.48 5179.78,1331.66 C1_AMP22.2@5196,1331.66 5196,1371.66 5186,1381.66 v1(5156,1381.66) 5156,1391.1 5211.43,1446.53 5281,1446.53 ; RC_SUMMER5.1@5204,2638.32 5204,2620.1 v1(5223,2601.1) ; CBi_SUMMER5.2@5216.22,2555.1 5216.22,2594.32 v1(5223,2601.1) ; Q1_AMP22.2@5232.34,2266.5 5232.34,2317.44 v1(5243,2328.1) ; C3_AMP22.1@5257,1571.1 5279.22,1571.1 ; v1@5260,2328.1 5286,2328.1 5286,1815.1 5285,1814.1 5281.5,1806.6 5281.5,1740.1 5300,1721.6 5300,1704.1 5312.78,1691.32 R3_AMP23.1@5321,1691.32 5282,1652.32 ; v1@5272,2039.1 5285,2039.1 ; v2@5280,1100.1 5280,1652.32 ; 5282.22,1598.66 CBi_AMP23.2@5303,1598.66 ; 5288.57,1910.54 Q2_AMP23.3@5336,1910.54 ; R19_AMP23.1@5346.78,1269.1 5346.78,1280.32 5338,1289.1 R1_AMP23.1@5338,1304.1 5358.59,1304.1 5358.59,1328.48 5361.78,1331.66 C1_AMP23.2@5378,1331.66 5378,1371.66 5368,1381.66 v1(5338,1381.66) 5338,1391.1 5393.43,1446.53 5463,1446.53 ; Q1_AMP23.2@5414.34,2266.5 5414.34,2317.44 v1(5425,2328.1) ; C3_AMP23.1@5439,1571.1 5461.22,1571.1 ; v1@5442,2328.1 5468,2328.1 5468,1815.1 5467,1814.1 5463.5,1806.6 5463.5,1740.1 5482,1721.6 5482,1704.1 5494.78,1691.32 R3_AMP24.1@5503,1691.32 5464,1652.32 ; v1@5454,2039.1 5467,2039.1 ; R17_SUMMER5.1@5457.78,2627.1 R14_SUMMER5.1@5457.78,2702.1 ; v2@5462,1100.1 5462,1652.32 ; 5464.22,1598.66 CBi_AMP24.2@5485,1598.66 ; 5470.57,1910.54 Q2_AMP24.3@5518,1910.54 ; R19_AMP24.1@5528.78,1269.1 5528.78,1280.32 5520,1289.1 R1_AMP24.1@5520,1304.1 5540.59,1304.1 5540.59,1328.48 5543.78,1331.66 C1_AMP24.2@5560,1331.66 5560,1371.66 5550,1381.66 v1(5520,1381.66) 5520,1391.1 5575.43,1446.53 5645,1446.53 ; Q1_AMP24.2@5596.34,2266.5 5596.34,2317.44 v1(5607,2328.1) ; C3_AMP24.1@5621,1571.1 5643.22,1571.1 ; v1@5624,2328.1 5650,2328.1 5650,1815.1 5649,1814.1 5645.5,1806.6 5645.5,1740.1 5664,1721.6 5664,1704.1 5676.78,1691.32 R3_AMP25.1@5685,1691.32 5646,1652.32 ; v1@5636,2039.1 5649,2039.1 ; v2@5644,1100.1 5644,1652.32 ; 5646.22,1598.66 CBi_AMP25.2@5667,1598.66 ; 5652.57,1910.54 Q2_AMP25.3@5700,1910.54 ; R19_AMP25.1@5710.78,1269.1 5710.78,1280.32 5702,1289.1 R1_AMP25.1@5702,1304.1 5722.59,1304.1 5722.59,1328.48 5725.78,1331.66 C1_AMP25.2@5742,1331.66 5742,1371.66 5732,1381.66 v1(5702,1381.66) 5702,1391.1 5757.43,1446.53 5827,1446.53 ; v1@5748.78,2675.32 CG_SUMMER5.2@5748.78,2720.1 ; Q1_AMP25.2@5778.34,2266.5 5778.34,2317.44 v1(5789,2328.1) ; C3_AMP25.1@5804,1571.57 5826.22,1571.57 ; v1@5807,2328.57 5833,2328.57 5833,1815.57 5832,1814.57 5828.5,1807.07 5828.5,1740.57 5847,1722.07 5847,1704.57 5859.78,1691.79 R3_AMP26.1@5868,1691.79 5829,1652.79 5829,1420.57 ; v1@5819,2039.57 5832,2039.57 ; v2@5826,1100.1 5826,1445.53 ; 5829.22,1599.13 CBi_AMP26.2@5850,1599.13 ; 5835.57,1911 Q2_AMP26.3@5883,1911 ; R19_AMP26.1@5893.78,1269.57 5893.78,1280.79 5885,1289.57 R1_AMP26.1@5885,1304.57 5905.59,1304.57 5905.59,1328.94 5908.78,1332.13 C1_AMP26.2@5925,1332.13 5925,1372.13 5915,1382.13 v1(5885,1382.13) 5885,1391.57 5940.43,1447 6010,1447 ; Q1_AMP26.2@5961.34,2266.97 5961.34,2317.91 v1(5972,2328.57) ; Q7_SUMMER6.3@5971,2540.14 5998.57,2540.14 6036,2577.57 Q6_SUMMER6.3@6036,2655.14 ; v1(5981,2461) 5987.65,2454.35 6044.78,2454.35 6075,2484.57 R12_SUMMER6.1@6126.22,2484.57 ; C3_AMP26.1@5986,1571.57 6008.22,1571.57 ; v1@5989,2328.57 6015,2328.57 6015,1815.57 6014,1814.57 6010.5,1807.07 6010.5,1740.57 6029,1722.07 6029,1704.57 6041.78,1691.79 R3_AMP27.1@6050,1691.79 6011,1652.79 ; v1@6001,2039.57 6014,2039.57 ; v2@6009,1100.57 6009,1652.79 ; 6011.22,1599.13 CBi_AMP27.2@6032,1599.13 ; 6017.57,1911 Q2_AMP27.3@6065,1911 ; 6036,2601.57 v1(6134,2601.57) ; D1.1@6051.26,3092.6 6104.6,3092.6 6104.6,3159.6 v1(6108,3163) ; R19_AMP27.1@6075.78,1269.57 6075.78,1280.79 6067,1289.57 R1_AMP27.1@6067,1304.57 6087.59,1304.57 6087.59,1328.94 6090.78,1332.13 C1_AMP27.2@6107,1332.13 6107,1372.13 6097,1382.13 v1(6067,1382.13) 6067,1391.57 6122.43,1447 6192,1447 ; RC_SUMMER6.1@6115,2638.79 6115,2620.57 v1(6134,2601.57) ; CBi_SUMMER6.2@6127.22,2555.57 6127.22,2594.79 v1(6134,2601.57) ; Q1_AMP27.2@6143.34,2266.97 6143.34,2317.91 v1(6154,2328.57) ; C3_AMP27.1@6168,1571.57 6190.22,1571.57 ; v1@6171,2328.57 6197,2328.57 6197,1815.57 6196,1814.57 6192.5,1807.07 6192.5,1740.57 6211,1722.07 6211,1704.57 6223.78,1691.79 R3_AMP28.1@6232,1691.79 6193,1652.79 ; v1@6183,2039.57 6196,2039.57 ; R27.2@6189,2954.54 v1@6245.54,2954.54 ; v2@6191,1100.57 6191,1652.79 ; 6193.22,1599.13 CBi_AMP28.2@6214,1599.13 ; 6199.57,1911 Q2_AMP28.3@6247,1911 ; R19_AMP28.1@6257.78,1269.57 6257.78,1280.79 6249,1289.57 R1_AMP28.1@6249,1304.57 6269.59,1304.57 6269.59,1328.94 6272.78,1332.13 C1_AMP28.2@6289,1332.13 6289,1372.13 6279,1382.13 v1(6249,1382.13) 6249,1391.57 6304.43,1447 6374,1447 ; Q1_AMP28.2@6325.34,2266.97 6325.34,2317.91 v1(6336,2328.57) ; C3_AMP28.1@6350,1571.57 6372.22,1571.57 ; v1@6353,2328.57 6379,2328.57 6379,1815.57 6378,1814.57 6374.5,1807.07 6374.5,1740.57 6393,1722.07 6393,1704.57 6405.78,1691.79 R3_AMP29.1@6414,1691.79 6375,1652.79 ; v1@6365,2039.57 6378,2039.57 ; R17_SUMMER6.1@6368.78,2627.57 R14_SUMMER6.1@6368.78,2702.57 ; v2@6373,1100.57 6373,1652.79 ; 6375.22,1599.13 CBi_AMP29.2@6396,1599.13 ; 6381.57,1911 Q2_AMP29.3@6429,1911 ; R19_AMP29.1@6439.78,1269.57 6439.78,1280.79 6431,1289.57 R1_AMP29.1@6431,1304.57 6451.59,1304.57 6451.59,1328.94 6454.78,1332.13 C1_AMP29.2@6471,1332.13 6471,1372.13 6461,1382.13 v1(6431,1382.13) 6431,1391.57 6486.43,1447 6556,1447 ; Q1_AMP29.2@6507.34,2266.97 6507.34,2317.91 v1(6518,2328.57) ; C3_AMP29.1@6532,1572 6554.22,1572 ; v1@6535,2329 6561,2329 6561,1816 6560,1815 6556.5,1807.5 6556.5,1741 6575,1722.5 6575,1705 6587.78,1692.22 R3_AMP30.1@6596,1692.22 6557,1653.22 ; v1@6547,2040 6560,2040 ; v2@6555,1100.57 6555,1653.22 ; 6557.22,1599.56 CBi_AMP30.2@6578,1599.56 ; 6563.57,1911.43 Q2_AMP30.3@6611,1911.43 ; R19_AMP30.1@6621.78,1270 6621.78,1281.22 6613,1290 R1_AMP30.1@6613,1305 6633.59,1305 6633.59,1329.37 6636.78,1332.56 C1_AMP30.2@6653,1332.56 6653,1372.56 6643,1382.56 v1(6613,1382.56) 6613,1392 6668.43,1447.43 6738,1447.43 6738,1569 ; v1@6659.78,2675.79 CG_SUMMER6.2@6659.78,2720.57 ; Q1_AMP30.2@6689.34,2267.4 6689.34,2318.34 v1(6700,2329) 6735,2329 6743,2321 6743,1736 6757,1722 6757,1588 6738,1569 ; C3_AMP30.1@6714,1572 6735,1572 6738,1569 ; v1(6715,2040) 6741,2040 6743,2042 ; v2(6739,1101) 6739,1446.43
  other v1: 1243,2039.43 1426,2039.43 1609,2039.43 1793,2039.43 1976,2039.43 2158,2039.43 2340,2039.43 2521,2039.43 2702,2039.43 2883,2039.43 3066,2039.43 3247,2039.43 3429,2039.43 3611,2039.43 3793,2039.43 3977,2039.43 4160,2039.43 4342,2039.43 4524,2039.43 4707,2039.43 4890,2039.53 5072,2039.53 5254,2039.53 5436,2039.53 5618,2039.53 5801,2040 5983,2040 6165,2040 6347,2040 6529,2040.43 1810.78,2664 2725.78,2664 3633.78,2664 4544.78,2664 5457.78,2664.1 6368.78,2664.57 2103,2674 3018,2674 3926,2674 4837,2674 5750,2674.1 6661,2674.57 6253,2962 1562.26,3175.26 1656,3252
  other v2: 5100,1100.1 5282,1100.1 5464,1100.1 5646,1100.1 5828,1100.1 6011,1100.57 6193,1100.57 6375,1100.57 6557,1100.57
NetC1_AMP1_1: C1_AMP1.1 R18_AMP1.2 SIPM_AMP1.2 | length 151.9
  Top Layer w5.09: C1_AMP1.1@1363.64,1305.65 1367,1305.65 R18_AMP1.2@1404,1305.65
  Top Layer w7: C1_AMP1.1@1367,1304 1367,1289 1407,1249 SIPM_AMP1.2@1407,1209
NetC1_AMP2_1: C1_AMP2.1 R18_AMP2.2 SIPM_AMP2.2 | length 151.9
  Top Layer w5.09: C1_AMP2.1@1546.64,1305.65 1550,1305.65 R18_AMP2.2@1587,1305.65
  Top Layer w7: C1_AMP2.1@1550,1304 1550,1289 1590,1249 SIPM_AMP2.2@1590,1209
NetC1_AMP3_1: C1_AMP3.1 R18_AMP3.2 SIPM_AMP3.2 | length 151.9
  Top Layer w5.09: C1_AMP3.1@1729.64,1305.65 1733,1305.65 R18_AMP3.2@1770,1305.65
  Top Layer w7: C1_AMP3.1@1733,1304 1733,1289 1773,1249 SIPM_AMP3.2@1773,1209
NetC1_AMP4_1: C1_AMP4.1 R18_AMP4.2 SIPM_AMP4.2 | length 151.9
  Top Layer w5.09: C1_AMP4.1@1913.64,1305.65 1917,1305.65 R18_AMP4.2@1954,1305.65
  Top Layer w7: C1_AMP4.1@1917,1304 1917,1289 1957,1249 SIPM_AMP4.2@1957,1209
NetC1_AMP5_1: C1_AMP5.1 R18_AMP5.2 SIPM_AMP5.2 | length 151.9
  Top Layer w5.09: C1_AMP5.1@2096.64,1305.65 2100,1305.65 R18_AMP5.2@2137,1305.65
  Top Layer w7: C1_AMP5.1@2100,1304 2100,1289 2140,1249 SIPM_AMP5.2@2140,1209
NetC1_AMP6_1: C1_AMP6.1 R18_AMP6.2 SIPM_AMP6.2 | length 151.9
  Top Layer w5.09: C1_AMP6.1@2278.64,1305.65 2282,1305.65 R18_AMP6.2@2319,1305.65
  Top Layer w7: C1_AMP6.1@2282,1304 2282,1289 2322,1249 SIPM_AMP6.2@2322,1209
NetC1_AMP7_1: C1_AMP7.1 R18_AMP7.2 SIPM_AMP7.2 | length 151.9
  Top Layer w5.09: C1_AMP7.1@2460.64,1305.65 2464,1305.65 R18_AMP7.2@2501,1305.65
  Top Layer w7: C1_AMP7.1@2464,1304 2464,1289 2504,1249 SIPM_AMP7.2@2504,1209
NetC1_AMP8_1: C1_AMP8.1 R18_AMP8.2 SIPM_AMP8.2 | length 151.9
  Top Layer w5.09: C1_AMP8.1@2641.64,1305.65 2645,1305.65 R18_AMP8.2@2682,1305.65
  Top Layer w7: C1_AMP8.1@2645,1304 2645,1289 2685,1249 SIPM_AMP8.2@2685,1209
NetC1_AMP9_1: C1_AMP9.1 R18_AMP9.2 SIPM_AMP9.2 | length 151.9
  Top Layer w5.09: C1_AMP9.1@2822.64,1305.65 2826,1305.65 R18_AMP9.2@2863,1305.65
  Top Layer w7: C1_AMP9.1@2826,1304 2826,1289 2866,1249 SIPM_AMP9.2@2866,1209
NetC1_AMP10_1: C1_AMP10.1 R18_AMP10.2 SIPM_AMP10.2 | length 151.9
  Top Layer w5.09: C1_AMP10.1@3003.64,1305.65 3007,1305.65 R18_AMP10.2@3044,1305.65
  Top Layer w7: C1_AMP10.1@3007,1304 3007,1289 3047,1249 SIPM_AMP10.2@3047,1209
NetC1_AMP11_1: C1_AMP11.1 R18_AMP11.2 SIPM_AMP11.2 | length 151.9
  Top Layer w5.09: C1_AMP11.1@3186.64,1305.65 3190,1305.65 R18_AMP11.2@3227,1305.65
  Top Layer w7: C1_AMP11.1@3190,1304 3190,1289 3230,1249 SIPM_AMP11.2@3230,1209
NetC1_AMP12_1: C1_AMP12.1 R18_AMP12.2 SIPM_AMP12.2 | length 151.9
  Top Layer w5.09: C1_AMP12.1@3367.64,1305.65 3371,1305.65 R18_AMP12.2@3408,1305.65
  Top Layer w7: C1_AMP12.1@3371,1304 3371,1289 3411,1249 SIPM_AMP12.2@3411,1209
NetC1_AMP13_1: C1_AMP13.1 R18_AMP13.2 SIPM_AMP13.2 | length 151.9
  Top Layer w5.09: C1_AMP13.1@3549.64,1305.65 3553,1305.65 R18_AMP13.2@3590,1305.65
  Top Layer w7: C1_AMP13.1@3553,1304 3553,1289 3593,1249 SIPM_AMP13.2@3593,1209
NetC1_AMP14_1: C1_AMP14.1 R18_AMP14.2 SIPM_AMP14.2 | length 151.9
  Top Layer w5.09: C1_AMP14.1@3731.64,1305.65 3735,1305.65 R18_AMP14.2@3772,1305.65
  Top Layer w7: C1_AMP14.1@3735,1304 3735,1289 3775,1249 SIPM_AMP14.2@3775,1209
NetC1_AMP15_1: C1_AMP15.1 R18_AMP15.2 SIPM_AMP15.2 | length 151.9
  Top Layer w5.09: C1_AMP15.1@3913.64,1305.65 3917,1305.65 R18_AMP15.2@3954,1305.65
  Top Layer w7: C1_AMP15.1@3917,1304 3917,1289 3957,1249 SIPM_AMP15.2@3957,1209
NetC1_AMP16_1: C1_AMP16.1 R18_AMP16.2 SIPM_AMP16.2 | length 151.9
  Top Layer w5.09: C1_AMP16.1@4097.64,1305.65 4101,1305.65 R18_AMP16.2@4138,1305.65
  Top Layer w7: C1_AMP16.1@4101,1304 4101,1289 4141,1249 SIPM_AMP16.2@4141,1209
NetC1_AMP17_1: C1_AMP17.1 R18_AMP17.2 SIPM_AMP17.2 | length 151.9
  Top Layer w5.09: C1_AMP17.1@4280.64,1305.65 4284,1305.65 R18_AMP17.2@4321,1305.65
  Top Layer w7: C1_AMP17.1@4284,1304 4284,1289 4324,1249 SIPM_AMP17.2@4324,1209
NetC1_AMP18_1: C1_AMP18.1 R18_AMP18.2 SIPM_AMP18.2 | length 151.9
  Top Layer w5.09: C1_AMP18.1@4462.64,1305.65 4466,1305.65 R18_AMP18.2@4503,1305.65
  Top Layer w7: C1_AMP18.1@4466,1304 4466,1289 4506,1249 SIPM_AMP18.2@4506,1209
NetC1_AMP19_1: C1_AMP19.1 R18_AMP19.2 SIPM_AMP19.2 | length 151.9
  Top Layer w5.09: C1_AMP19.1@4644.64,1305.65 4648,1305.65 R18_AMP19.2@4685,1305.65
  Top Layer w7: C1_AMP19.1@4648,1304 4648,1289 4688,1249 SIPM_AMP19.2@4688,1209
NetC1_AMP20_1: C1_AMP20.1 R18_AMP20.2 SIPM_AMP20.2 | length 151.9
  Top Layer w5.09: C1_AMP20.1@4827.64,1305.65 4831,1305.65 R18_AMP20.2@4868,1305.65
  Top Layer w7: C1_AMP20.1@4831,1304 4831,1289 4871,1249 SIPM_AMP20.2@4871,1209
NetC1_AMP21_1: C1_AMP21.1 R18_AMP21.2 SIPM_AMP21.2 | length 151.9
  Top Layer w5.09: C1_AMP21.1@5010.64,1305.75 5014,1305.75 R18_AMP21.2@5051,1305.75
  Top Layer w7: C1_AMP21.1@5014,1304.1 5014,1289.1 5054,1249.1 SIPM_AMP21.2@5054,1209.1
NetC1_AMP22_1: C1_AMP22.1 R18_AMP22.2 SIPM_AMP22.2 | length 151.9
  Top Layer w5.09: C1_AMP22.1@5192.64,1305.75 5196,1305.75 R18_AMP22.2@5233,1305.75
  Top Layer w7: C1_AMP22.1@5196,1304.1 5196,1289.1 5236,1249.1 SIPM_AMP22.2@5236,1209.1
NetC1_AMP23_1: C1_AMP23.1 R18_AMP23.2 SIPM_AMP23.2 | length 151.9
  Top Layer w5.09: C1_AMP23.1@5374.64,1305.75 5378,1305.75 R18_AMP23.2@5415,1305.75
  Top Layer w7: C1_AMP23.1@5378,1304.1 5378,1289.1 5418,1249.1 SIPM_AMP23.2@5418,1209.1
NetC1_AMP24_1: C1_AMP24.1 R18_AMP24.2 SIPM_AMP24.2 | length 151.9
  Top Layer w5.09: C1_AMP24.1@5556.64,1305.75 5560,1305.75 R18_AMP24.2@5597,1305.75
  Top Layer w7: C1_AMP24.1@5560,1304.1 5560,1289.1 5600,1249.1 SIPM_AMP24.2@5600,1209.1
NetC1_AMP25_1: C1_AMP25.1 R18_AMP25.2 SIPM_AMP25.2 | length 151.9
  Top Layer w5.09: C1_AMP25.1@5738.64,1305.75 5742,1305.75 R18_AMP25.2@5779,1305.75
  Top Layer w7: C1_AMP25.1@5742,1304.1 5742,1289.1 5782,1249.1 SIPM_AMP25.2@5782,1209.1
NetC1_AMP26_1: C1_AMP26.1 R18_AMP26.2 SIPM_AMP26.2 | length 151.9
  Top Layer w5.09: C1_AMP26.1@5921.64,1306.22 5925,1306.22 R18_AMP26.2@5962,1306.22
  Top Layer w7: C1_AMP26.1@5925,1304.57 5925,1289.57 5965,1249.57 SIPM_AMP26.2@5965,1209.57
NetC1_AMP27_1: C1_AMP27.1 R18_AMP27.2 SIPM_AMP27.2 | length 151.9
  Top Layer w5.09: C1_AMP27.1@6103.64,1306.22 6107,1306.22 R18_AMP27.2@6144,1306.22
  Top Layer w7: C1_AMP27.1@6107,1304.57 6107,1289.57 6147,1249.57 SIPM_AMP27.2@6147,1209.57
NetC1_AMP28_1: C1_AMP28.1 R18_AMP28.2 SIPM_AMP28.2 | length 151.9
  Top Layer w5.09: C1_AMP28.1@6285.64,1306.22 6289,1306.22 R18_AMP28.2@6326,1306.22
  Top Layer w7: C1_AMP28.1@6289,1304.57 6289,1289.57 6329,1249.57 SIPM_AMP28.2@6329,1209.57
NetC1_AMP29_1: C1_AMP29.1 R18_AMP29.2 SIPM_AMP29.2 | length 151.9
  Top Layer w5.09: C1_AMP29.1@6467.64,1306.22 6471,1306.22 R18_AMP29.2@6508,1306.22
  Top Layer w7: C1_AMP29.1@6471,1304.57 6471,1289.57 6511,1249.57 SIPM_AMP29.2@6511,1209.57
NetC1_AMP30_1: C1_AMP30.1 R18_AMP30.2 SIPM_AMP30.2 | length 151.9
  Top Layer w5.09: C1_AMP30.1@6649.64,1306.65 6653,1306.65 R18_AMP30.2@6690,1306.65
  Top Layer w7: C1_AMP30.1@6653,1305 6653,1290 6693,1250 SIPM_AMP30.2@6693,1210
NetC2_AMP1_1: C2_AMP1.1 R19_AMP1.2 SIPM_AMP1.1 | length 98.4
  Top Layer w7: C2_AMP1.1@1297,1304 1297,1291.88 1308.22,1280.66 R19_AMP1.2@1308.22,1269 SIPM_AMP1.1@1308.22,1210.22
NetC2_AMP1_2: C2_AMP1.2 Q0_AMP1.2 R1_AMP1.2 | length 152.2
  Top Layer w7: Q0_AMP1.2@1307,1442.6 1307,1431.56 1288.5,1413.06 1288.5,1365.93 1297,1357.43 C2_AMP1.2@1297,1331.56 R1_AMP1.2@1327,1331.56
NetC2_AMP2_1: C2_AMP2.1 R19_AMP2.2 SIPM_AMP2.1 | length 98.4
  Top Layer w7: C2_AMP2.1@1480,1304 1480,1291.88 1491.22,1280.66 R19_AMP2.2@1491.22,1269 SIPM_AMP2.1@1491.22,1210.22
NetC2_AMP2_2: C2_AMP2.2 Q0_AMP2.2 R1_AMP2.2 | length 152.2
  Top Layer w7: Q0_AMP2.2@1490,1442.6 1490,1431.56 1471.5,1413.06 1471.5,1365.93 1480,1357.43 C2_AMP2.2@1480,1331.56 R1_AMP2.2@1510,1331.56
NetC2_AMP3_1: C2_AMP3.1 R19_AMP3.2 SIPM_AMP3.1 | length 98.4
  Top Layer w7: C2_AMP3.1@1663,1304 1663,1291.88 1674.22,1280.66 R19_AMP3.2@1674.22,1269 SIPM_AMP3.1@1674.22,1210.22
